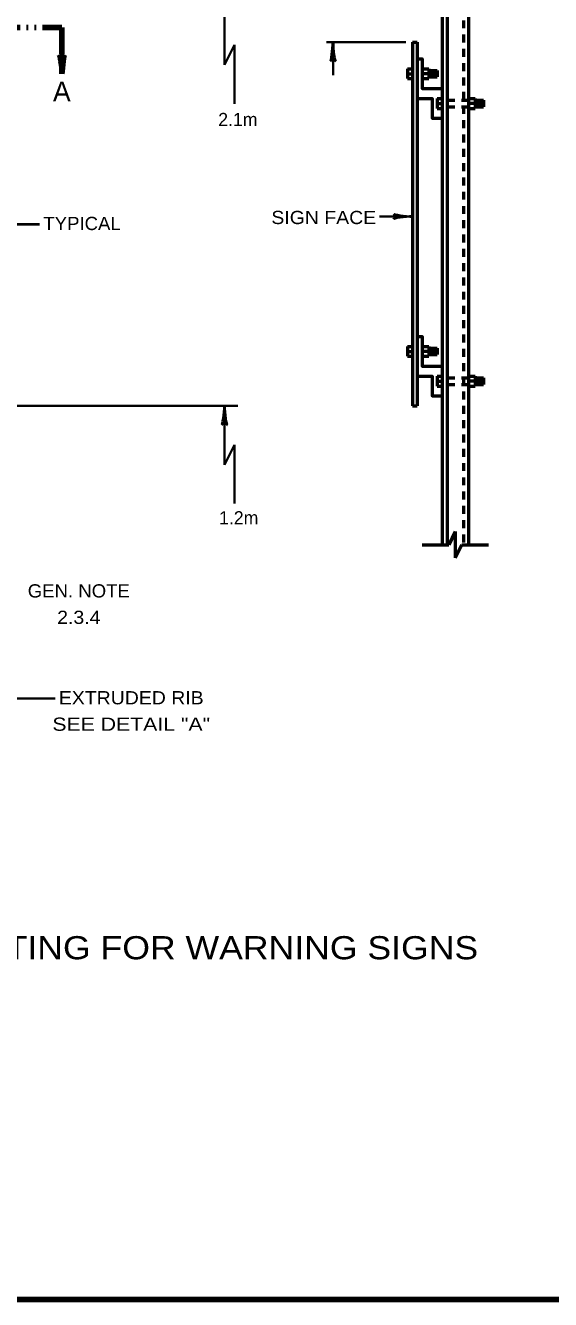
# Model space of a CAD drawing. Extents: x -87 to 768, y -466 to 78.
# Drawn here: x 374.6 to 469.9, y -454.3 to -223 of the extents above; entities that cross this region are included whole.
import ezdxf
from ezdxf.enums import TextEntityAlignment as Align

# ---------------------------------------------------------------- set-up
doc = ezdxf.new("R2010")
doc.units = 0
doc.header["$LTSCALE"] = 0.96
doc.linetypes.add('DASH_DOUBLE_DOT', pattern=[9.2, 5, -1.2, 0.3, -1.2, 0.3, -1.2])
doc.linetypes.add('SHORT_DASHED', pattern=[2.7, 1.5, -1.2])
doc.layers.add('1', color=7, linetype='Continuous', lineweight=53)

msp = doc.modelspace()

# ---------------------------------------------------------------- linework, layer by layer
at = {"layer": '1'}
for p, q in [((450.1887, -84.7407), (450.1887, -317.295)), ((451.0887, -84.7407), (451.0887, -317.295)), ((454.9887, -84.7407), (454.9887, -317.295)), ((444.7887, -226.095), (444.7887, -292.095)), ((444.7887, -226.095), (445.6887, -226.095)), ((445.6887, -226.095), (445.6887, -292.095)), ((443.8887, -230.895), (444.7887, -230.895)), ((443.8887, -230.895), (443.8887, -232.695)), ((446.5887, -230.895), (447.7887, -230.895)), ((447.7887, -230.895), (447.7887, -232.695)), ((447.7887, -231.195), (449.2887, -231.195)), ((448.0887, -231.195), (448.0887, -232.395)), ((448.6887, -231.195), (448.6887, -232.395)), ((449.2887, -231.195), (449.2887, -232.395)), ((443.8887, -231.795), (444.7887, -231.795)), ((443.8887, -232.695), (444.7887, -232.695)), ((447.7887, -231.795), (446.5887, -231.795)), ((446.5887, -232.695), (447.7887, -232.695)), ((447.7887, -232.395), (449.2887, -232.395)), ((448.3887, -231.495), (448.3887, -232.095)), ((448.9887, -231.495), (448.9887, -232.095)), ((449.2887, -236.295), (450.1887, -236.295)), ((449.2887, -236.295), (449.2887, -238.095)), ((449.2887, -237.195), (450.1887, -237.195)), ((449.2887, -238.095), (450.1887, -238.095)), ((454.9887, -236.295), (456.1887, -236.295)), ((456.1887, -237.195), (454.9887, -237.195)), ((454.9887, -238.095), (456.1887, -238.095)), ((456.1887, -236.295), (456.1887, -238.095)), ((456.1887, -236.595), (457.6887, -236.595)), ((456.1887, -237.795), (457.6887, -237.795)), ((456.4887, -236.595), (456.4887, -237.795)), ((456.7887, -236.895), (456.7887, -237.495)), ((457.0887, -236.595), (457.0887, -237.795)), ((457.3887, -236.895), (457.3887, -237.495)), ((457.6887, -236.595), (457.6887, -237.795)), ((443.8887, -281.295), (444.7887, -281.295)), ((443.8887, -281.295), (443.8887, -283.095)), ((446.5887, -281.295), (447.7887, -281.295)), ((447.7887, -281.295), (447.7887, -283.095)), ((447.7887, -281.595), (449.2887, -281.595)), ((448.0887, -281.595), (448.0887, -282.795)), ((448.3887, -281.895), (448.3887, -282.495)), ((448.6887, -281.595), (448.6887, -282.795)), ((448.9887, -281.895), (448.9887, -282.495)), ((449.2887, -281.595), (449.2887, -282.795)), ((443.8887, -282.195), (444.7887, -282.195)), ((443.8887, -283.095), (444.7887, -283.095)), ((447.7887, -282.195), (446.5887, -282.195)), ((446.5887, -283.095), (447.7887, -283.095)), ((447.7887, -282.795), (449.2887, -282.795)), ((449.2887, -286.695), (450.1887, -286.695)), ((449.2887, -286.695), (449.2887, -288.495)), ((454.9887, -286.695), (456.1887, -286.695)), ((456.1887, -286.695), (456.1887, -288.495)), ((449.2887, -287.595), (450.1887, -287.595)), ((449.2887, -288.495), (450.1887, -288.495)), ((456.1887, -287.595), (454.9887, -287.595)), ((454.9887, -288.495), (456.1887, -288.495)), ((456.1887, -286.995), (457.6887, -286.995)), ((456.1887, -288.195), (457.6887, -288.195)), ((456.4887, -286.995), (456.4887, -288.195)), ((456.7887, -287.295), (456.7887, -287.895)), ((457.0887, -286.995), (457.0887, -288.195)), ((457.3887, -287.295), (457.3887, -287.895)), ((457.6887, -286.995), (457.6887, -288.195)), ((444.7887, -292.095), (445.6887, -292.095)), ((452.5887, -314.895), (451.3887, -317.295)), ((452.5887, -314.895), (452.5887, -319.695)), ((446.5887, -317.295), (451.3887, -317.295)), ((452.5887, -319.695), (453.7887, -317.295)), ((453.7887, -317.295), (458.5887, -317.295))]:
    msp.add_line(p, q, dxfattribs=at)
at = {"layer": '1', "linetype": 'SHORT_DASHED'}
for p, q in [((454.0887, -84.7407), (454.0887, -317.295)), ((451.0887, -236.595), (454.9887, -236.595)), ((451.0887, -237.795), (454.9887, -237.795)), ((451.0887, -286.995), (454.9887, -286.995)), ((451.0887, -288.195), (454.9887, -288.195))]:
    msp.add_line(p, q, dxfattribs=at)
at = {"layer": '1', "lineweight": 35}
for p, q in [((410.7002, -219.5093), (410.7002, -230.2068)), ((410.7002, -230.2068), (412.5376, -226.5549)), ((412.5376, -226.5549), (412.5376, -237.2524)), ((443.5887, -226.095), (429.1887, -226.095)), ((430.3887, -226.095), (430.3887, -232.095)), ((444.8152, -257.7234), (438.8152, -257.7234)), ((348.7887, -292.095), (413.1002, -292.095)), ((410.7002, -292.095), (410.7002, -302.7925)), ((410.7002, -302.7925), (412.5376, -299.1406)), ((412.5376, -299.1406), (412.5376, -309.8381)), ((367.9887, -345.195), (379.9887, -345.195))]:
    msp.add_line(p, q, dxfattribs=at)
at = {"layer": '1', "linetype": 'DASH_DOUBLE_DOT', "lineweight": 106}
for p, q in [((253.9887, -223.395), (381.1887, -223.395)), ((381.1887, -223.395), (381.1887, -231.795))]:
    msp.add_line(p, q, dxfattribs=at)
at = {"layer": '1', "lineweight": 40}
msp.add_line((350.5887, -259.095), (377.1397, -259.095), dxfattribs=at)
at = {"layer": '1', "lineweight": 158}
msp.add_line((761.8126, -454.2894), (-29.7874, -454.2894), dxfattribs=at)
at = {"layer": '1'}
for points in [[(445.6887, -229.095), (446.5887, -229.095), (446.5887, -234.495), (450.1887, -234.495)], [(445.6887, -236.295), (448.3887, -236.295), (448.3887, -239.895), (450.1887, -239.895)], [(445.6887, -279.495), (446.5887, -279.495), (446.5887, -284.895), (450.1887, -284.895)], [(445.6887, -286.695), (448.3887, -286.695), (448.3887, -290.295), (450.1887, -290.295)]]:
    msp.add_lwpolyline(points, dxfattribs=at)
at = {"layer": '1', "lineweight": 40}
for centre, major_axis, ratio, start_param, end_param in [((430.1348, -227.4396), (0.2108, 2.1077), 0.07063, 3.14071475, 5.41810995), ((430.7203, -227.4044), (-0.1874, 2.1428), 0.122415, 0.89635335, 3.14159265), ((443.5058, -258.055), (2.1428, 0.1874), 0.122415, 0.89635335, 3.14159265), ((443.4706, -257.4695), (2.1077, -0.2108), 0.07063, 3.14071475, 5.41810995), ((410.4463, -293.4396), (0.2108, 2.1077), 0.07063, 3.14071475, 5.41810995), ((411.0318, -293.4044), (-0.1874, 2.1428), 0.122415, 0.89635335, 3.14159265)]:
    msp.add_ellipse(centre, major_axis=major_axis, ratio=ratio, start_param=start_param, end_param=end_param, dxfattribs=at)
at = {"layer": '1', "lineweight": 106}
for centre, major_axis, ratio, start_param, end_param in [((380.8571, -230.4856), (0.1874, -2.1428), 0.122415, 0.89635335, 3.14159265), ((381.4426, -230.4504), (-0.2108, -2.1077), 0.07063, 3.14071475, 5.41810995)]:
    msp.add_ellipse(centre, major_axis=major_axis, ratio=ratio, start_param=start_param, end_param=end_param, dxfattribs=at)

# ---------------------------------------------------------------- texts
at = {"layer": '1'}
for s, height, p in [('A', 3.6, (381.1677, -236.822)), ('2.1m', 2.4, (413.1217, -241.3109)), ('1.2m', 2.4, (413.2748, -313.6041))]:
    msp.add_text(s, height=height, dxfattribs=at).set_placement(p, align=Align.CENTER)
for s, height, width, p in [('SIGN FACE', 2.4, 1.1, (428.7139, -259.0943)), ('TYPICAL', 2.4, 1.05, (384.8371, -260.1811)), ('GEN. NOTE', 2.4, 1.05, (384.2504, -326.8672)), ('2.3.4', 2.4, 1.1, (384.2504, -331.6672)), ('EXTRUDED RIB', 2.4, 1.1, (393.7695, -346.2644)), ('SEE DETAIL "A"', 2.4, 1.2, (393.7695, -351.0644)), ('TYPICAL TWO-POST MOUNTING FOR WARNING SIGNS', 4.2, 1.15, (371.3302, -392.5361))]:
    msp.add_text(s, height=height, dxfattribs=dict(at, width=width)).set_placement(p, align=Align.CENTER)

doc.saveas('drawing.dxf')
